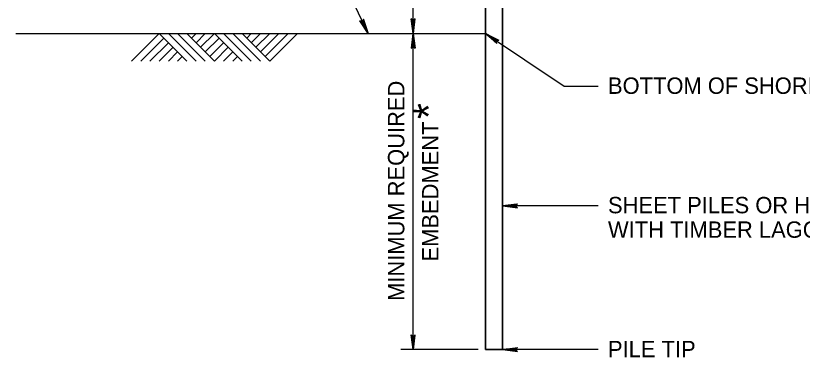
# Model space of a CAD drawing. Extents: x 1252282 to 1252638, y 733735 to 733845.
# Drawn here: x 1252538.76 to 1252571.3, y 733756.06 to 733770.2 of the extents above; entities that cross this region are included whole.
import ezdxf

# ---------------------------------------------------------------- set-up
doc = ezdxf.new("R2010")
doc.units = 0
doc.layers.add('Default', color=7, linetype='Continuous')

msp = doc.modelspace()

# ---------------------------------------------------------------- linework, layer by layer
at = {"layer": 'Default'}
for p, q in [((1252555.205, 733756.376), (1252555.205, 733785.595)), ((1252558.197, 733785.595), (1252558.197, 733769.461)), ((1252558.197, 733769.461), (1252558.197, 733785.595)), ((1252558.904, 733769.461), (1252558.904, 733785.595)), ((1252558.904, 733769.461), (1252558.904, 733785.595)), ((1252553.338, 733769.461), (1252553.002, 733769.979)), ((1252553.11, 733769.943), (1252553.002, 733769.979)), ((1252553.338, 733769.461), (1252553.017, 733769.974)), ((1252553.033, 733769.968), (1252553.338, 733769.461)), ((1252553.338, 733769.461), (1252553.048, 733769.963)), ((1252553.064, 733769.958), (1252553.338, 733769.461)), ((1252553.338, 733769.461), (1252553.079, 733769.954)), ((1252553.095, 733769.948), (1252553.338, 733769.461)), ((1252553.151, 733770.05), (1252553.11, 733769.943)), ((1252553.11, 733769.943), (1252553.338, 733769.461)), ((1252553.338, 733769.461), (1252553.116, 733769.958)), ((1252553.122, 733769.974), (1252553.338, 733769.461)), ((1252553.338, 733769.461), (1252553.128, 733769.988)), ((1252553.134, 733770.004), (1252553.338, 733769.461)), ((1252553.338, 733769.461), (1252553.14, 733770.019)), ((1252553.146, 733770.035), (1252553.338, 733769.461)), ((1252553.338, 733769.461), (1252553.151, 733770.05)), ((1252555.205, 733769.461), (1252555.123, 733770.073)), ((1252555.205, 733769.994), (1252555.123, 733770.073)), ((1252555.205, 733769.461), (1252555.135, 733770.062)), ((1252555.146, 733770.05), (1252555.205, 733769.461)), ((1252555.205, 733769.461), (1252555.158, 733770.039)), ((1252555.17, 733770.027), (1252555.205, 733769.461)), ((1252555.205, 733769.461), (1252555.182, 733770.017)), ((1252555.194, 733770.005), (1252555.205, 733769.461)), ((1252555.205, 733769.461), (1252555.288, 733770.073)), ((1252555.288, 733770.073), (1252555.205, 733769.994)), ((1252555.277, 733770.062), (1252555.205, 733769.461)), ((1252555.205, 733769.461), (1252555.265, 733770.05)), ((1252555.253, 733770.039), (1252555.205, 733769.461)), ((1252555.205, 733769.461), (1252555.24, 733770.027)), ((1252555.229, 733770.017), (1252555.205, 733769.461)), ((1252555.205, 733769.461), (1252555.218, 733770.005)), ((1252555.205, 733769.994), (1252555.205, 733769.461)), ((1252538.761, 733769.461), (1252558.197, 733769.461)), ((1252543.552, 733768.317), (1252544.696, 733769.461)), ((1252544.696, 733769.461), (1252545.839, 733768.317)), ((1252545.077, 733769.461), (1252546.221, 733768.317)), ((1252545.458, 733769.461), (1252546.602, 733768.317)), ((1252545.839, 733769.461), (1252546.983, 733768.317)), ((1252546.03, 733769.27), (1252546.221, 733769.461)), ((1252546.221, 733769.079), (1252546.602, 733769.461)), ((1252546.411, 733768.889), (1252546.983, 733769.461)), ((1252546.983, 733769.461), (1252548.127, 733768.317)), ((1252547.364, 733769.461), (1252548.508, 733768.317)), ((1252547.746, 733769.461), (1252548.889, 733768.317)), ((1252548.127, 733769.461), (1252549.271, 733768.317)), ((1252548.317, 733769.27), (1252548.508, 733769.461)), ((1252548.508, 733769.079), (1252548.889, 733769.461)), ((1252548.699, 733768.889), (1252549.271, 733769.461)), ((1252548.889, 733768.698), (1252549.652, 733769.461)), ((1252549.08, 733768.507), (1252550.033, 733769.461)), ((1252549.271, 733768.317), (1252550.414, 733769.461)), ((1252555.205, 733769.461), (1252555.122, 733768.848)), ((1252555.134, 733768.859), (1252555.205, 733769.461)), ((1252555.205, 733769.461), (1252555.146, 733768.871)), ((1252555.158, 733768.882), (1252555.205, 733769.461)), ((1252555.205, 733769.461), (1252555.17, 733768.894)), ((1252555.181, 733768.904), (1252555.205, 733769.461)), ((1252555.205, 733769.461), (1252555.193, 733768.916)), ((1252555.205, 733769.461), (1252555.288, 733768.848)), ((1252555.205, 733768.927), (1252555.205, 733769.461)), ((1252555.217, 733768.916), (1252555.205, 733769.461)), ((1252555.205, 733769.461), (1252555.229, 733768.904)), ((1252555.24, 733768.894), (1252555.205, 733769.461)), ((1252555.205, 733769.461), (1252555.253, 733768.882)), ((1252555.265, 733768.871), (1252555.205, 733769.461)), ((1252555.205, 733769.461), (1252555.276, 733768.859)), ((1252558.197, 733756.376), (1252558.197, 733769.461)), ((1252558.197, 733769.461), (1252558.197, 733756.376)), ((1252558.197, 733769.461), (1252561.455, 733767.279)), ((1252558.197, 733769.461), (1252558.752, 733769.188)), ((1252558.197, 733769.461), (1252558.66, 733769.051)), ((1252558.657, 733769.067), (1252558.197, 733769.461)), ((1252558.197, 733769.461), (1252558.654, 733769.083)), ((1252558.651, 733769.099), (1252558.197, 733769.461)), ((1252558.197, 733769.461), (1252558.649, 733769.116)), ((1252558.646, 733769.131), (1252558.197, 733769.461)), ((1252558.197, 733769.461), (1252558.643, 733769.147)), ((1252558.64, 733769.164), (1252558.197, 733769.461)), ((1252558.656, 733769.167), (1252558.197, 733769.461)), ((1252558.197, 733769.461), (1252558.672, 733769.17)), ((1252558.688, 733769.174), (1252558.197, 733769.461)), ((1252558.197, 733769.461), (1252558.704, 733769.178)), ((1252558.72, 733769.182), (1252558.197, 733769.461)), ((1252558.197, 733769.461), (1252558.736, 733769.185)), ((1252558.904, 733756.376), (1252558.904, 733769.461)), ((1252558.904, 733756.376), (1252558.904, 733769.461)), ((1252543.933, 733768.317), (1252544.886, 733769.27)), ((1252546.602, 733768.698), (1252547.174, 733769.27)), ((1252558.64, 733769.164), (1252558.752, 733769.188)), ((1252558.66, 733769.051), (1252558.64, 733769.164)), ((1252544.315, 733768.317), (1252545.077, 733769.079)), ((1252544.696, 733768.317), (1252545.268, 733768.889)), ((1252546.793, 733768.507), (1252547.364, 733769.079)), ((1252546.983, 733768.317), (1252547.555, 733768.889)), ((1252555.122, 733768.848), (1252555.205, 733768.927)), ((1252555.205, 733768.927), (1252555.288, 733768.848)), ((1252545.077, 733768.317), (1252545.458, 733768.698)), ((1252545.458, 733768.317), (1252545.649, 733768.507)), ((1252547.364, 733768.317), (1252547.746, 733768.698)), ((1252547.746, 733768.317), (1252547.936, 733768.507)), ((1252561.455, 733767.279), (1252562.863, 733767.279)), ((1252558.904, 733762.334), (1252559.516, 733762.417)), ((1252558.904, 733762.334), (1252559.505, 733762.405)), ((1252559.493, 733762.394), (1252558.904, 733762.334)), ((1252558.904, 733762.334), (1252559.482, 733762.382)), ((1252559.471, 733762.369), (1252558.904, 733762.334)), ((1252558.904, 733762.334), (1252559.46, 733762.358)), ((1252559.448, 733762.346), (1252558.904, 733762.334)), ((1252558.904, 733762.334), (1252559.516, 733762.251)), ((1252559.505, 733762.263), (1252558.904, 733762.334)), ((1252558.904, 733762.334), (1252559.493, 733762.275)), ((1252559.482, 733762.287), (1252558.904, 733762.334)), ((1252558.904, 733762.334), (1252559.471, 733762.299)), ((1252559.46, 733762.31), (1252558.904, 733762.334)), ((1252558.904, 733762.334), (1252559.448, 733762.322)), ((1252559.437, 733762.334), (1252558.904, 733762.334)), ((1252562.863, 733762.334), (1252558.904, 733762.334)), ((1252559.437, 733762.334), (1252559.516, 733762.417)), ((1252559.516, 733762.251), (1252559.437, 733762.334)), ((1252555.205, 733756.376), (1252555.123, 733756.988)), ((1252555.205, 733756.909), (1252555.123, 733756.988)), ((1252555.205, 733756.376), (1252555.135, 733756.977)), ((1252555.146, 733756.965), (1252555.205, 733756.376)), ((1252555.205, 733756.376), (1252555.158, 733756.954)), ((1252555.17, 733756.942), (1252555.205, 733756.376)), ((1252555.205, 733756.376), (1252555.182, 733756.932)), ((1252555.194, 733756.92), (1252555.205, 733756.376)), ((1252555.205, 733756.376), (1252555.288, 733756.988)), ((1252555.288, 733756.988), (1252555.205, 733756.909)), ((1252555.277, 733756.977), (1252555.205, 733756.376)), ((1252555.205, 733756.376), (1252555.265, 733756.965)), ((1252555.253, 733756.954), (1252555.205, 733756.376)), ((1252555.205, 733756.376), (1252555.24, 733756.942)), ((1252555.229, 733756.932), (1252555.205, 733756.376)), ((1252555.205, 733756.376), (1252555.218, 733756.92)), ((1252555.205, 733756.909), (1252555.205, 733756.376)), ((1252558.904, 733756.376), (1252559.516, 733756.458)), ((1252558.904, 733756.376), (1252559.505, 733756.446)), ((1252559.493, 733756.435), (1252558.904, 733756.376)), ((1252558.904, 733756.376), (1252559.482, 733756.423)), ((1252559.437, 733756.376), (1252559.516, 733756.458)), ((1252557.894, 733756.376), (1252554.7, 733756.376)), ((1252558.197, 733756.376), (1252558.904, 733756.376)), ((1252558.197, 733756.376), (1252558.904, 733756.376)), ((1252559.471, 733756.411), (1252558.904, 733756.376)), ((1252558.904, 733756.376), (1252559.46, 733756.399)), ((1252559.448, 733756.387), (1252558.904, 733756.376)), ((1252558.904, 733756.376), (1252559.516, 733756.293)), ((1252559.505, 733756.304), (1252558.904, 733756.376)), ((1252558.904, 733756.376), (1252559.493, 733756.316)), ((1252559.482, 733756.328), (1252558.904, 733756.376)), ((1252558.904, 733756.376), (1252559.471, 733756.341)), ((1252559.46, 733756.352), (1252558.904, 733756.376)), ((1252558.904, 733756.376), (1252559.448, 733756.363)), ((1252559.437, 733756.376), (1252558.904, 733756.376)), ((1252562.863, 733756.376), (1252558.904, 733756.376)), ((1252559.516, 733756.293), (1252559.437, 733756.376))]:
    msp.add_line(p, q, dxfattribs=at)
msp.add_lwpolyline([(1252558.197, 733785.595), (1252558.904, 733785.595), (1252558.904, 733756.376), (1252558.197, 733756.376)], close=True, dxfattribs=at)
msp.add_lwpolyline([(1252553.338, 733769.461), (1252551.728, 733772.868), (1252550.319, 733772.868)], dxfattribs=at)

# ---------------------------------------------------------------- texts
for s, height, p in [('BOTTOM OF SHORING', 0.67788, (1252563.265, 733766.963)), ('SHEET PILES OR H-PILES', 0.67788, (1252563.265, 733762.019)), ('WITH TIMBER LAGGING', 0.67788, (1252563.265, 733761.005)), ('PILE TIP', 0.6779, (1252563.265, 733756.06))]:
    msp.add_text(s, height=height, dxfattribs=at).set_placement(p)
for s, height, p in [('MINIMUM REQUIRED', 0.67788, (1252554.839, 733758.392)), ('*', 1.271, (1252556.483, 733765.918)), ('EMBEDMENT', 0.6779, (1252556.25, 733760.025))]:
    msp.add_text(s, height=height, rotation=90, dxfattribs=at).set_placement(p)

doc.saveas('drawing.dxf')
